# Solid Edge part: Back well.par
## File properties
Username: m_hel
Author: m_hel
Template: Iso Metric Part.par
Last saved by: m_hel
Revision: 10
Application: Solid Edge
Accuracy: 0,990
Material: Textured White
Face Style: White painted
Fill Style: ANSI36(Marble)
Virtual Style: ANSI36(Marble)
Grouping: Uncategorized
LibraryName: Custom Materials
Coef. of Thermal Exp: 0.0
Thermal Conductivity: 0.0
Specific Heat: 0.0
Modulus of Elasticity: 0.0
Poisson's Ratio: 0.0
Yield Stress: 0.0
Ultimate Stress: 0.0
Elongation: 0.0
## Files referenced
..\..\Redfisher18.asm
G:\OneDriveTemp\OneDrive\Dokumendid\TLÜ tööd\3D Modelleerimine\3d modelling\veesõiduk\Deck1.par
G:\OneDriveTemp\OneDrive\Dokumendid\TLÜ tööd\3D Modelleerimine\3d modelling\veesõiduk\Hull.par
iduk\Deck1.par
iduk\Hull.par
iduk\Redfisher18.asm
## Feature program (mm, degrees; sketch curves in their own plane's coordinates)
sketch for "unnamed Protrusion 1" plane through (0, 0, 0) normal (0, 0, 1) x-axis (1, 0, 0)
  line (393.4533, -2800) -> (-393.4533, -2800)
  line (-304.3712, -2294.7906) -> (-393.4533, -2800)
  arc centre (-274.827, -2300) radius 30 from (-274.827, -2270) to (-304.3712, -2294.7906) ccw
  line (274.827, -2270) -> (-274.827, -2270)
  arc centre (274.827, -2300) radius 30 from (304.3712, -2294.7906) to (274.827, -2270) ccw
  line (393.4533, -2800) -> (304.3712, -2294.7906)
extrude "unnamed Protrusion 1" add finite 300 along -normal
thinwall "Thinwall_1"  Thickness = 20 mm
fillet "Round_1" radius 30
lofted protrusion "LoftedProtrusion_1"  StartTangentMagnitude1 = 1; EndTangentMagnitude1 = 1
sketch for "unnamed Cutout 1" plane through (281.2863, -2451.808, -107.6654) normal (-0.984808, -0.173648, 0) x-axis (0.173648, -0.984808, 0)
  circle centre (0, 0) radius 25
extrude "unnamed Cutout 1" cut through along -normal
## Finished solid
Body 1: solid body, 30 faces, 70 edges, 42 vertices.
  Faces by surface: cylinder 11, plane 11, spline 4, sphere 2, torus 2
  Edges by curve: line 38, circle 24, ellipse 4, spline 4
Bounding box of the edges (mm; curved faces can reach further): 827.524 x 550.000 x 320.000, from (-413.7618, -2800, -320) to (413.7618, -2250, 0).
Cylindrical faces by radius (mm): R25 x1, R30 x8, R50 x2
Toroidal faces (ring radius, tube radius in mm): R20 r30 x2
Spherical faces by radius (mm): R30 x2
Planar faces by outward normal: +y 1, +z 2, -y 2, -z 1, oblique 5
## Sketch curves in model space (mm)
circle centre (281.2863, -2451.808, -107.6654) radius 37.5
line (-304.3712, -2294.7906, 0) -> (-393.4533, -2800, 0)
arc centre (-274.827, -2300, 0) radius 30 from (-274.827, -2270, 0) through (-294.1106, -2277.0187, 0) to (-304.3712, -2294.7906, 0)
line (274.827, -2270, 0) -> (-274.827, -2270, 0)
arc centre (274.827, -2300, 0) radius 30 from (304.3712, -2294.7906, 0) through (294.1106, -2277.0187, 0) to (274.827, -2270, 0)
line (393.4533, -2800, 0) -> (304.3712, -2294.7906, 0)
line (393.4533, -2800, 0) -> (-393.4533, -2800, 0)
line (339.2091, -2492.366, -157.6654) -> (339.2091, -2492.366, -57.6654)
line (339.2091, -2492.366, -57.6654) -> (321.8443, -2393.8852, -57.6654)
line (321.8443, -2393.8852, -57.6654) -> (321.8443, -2393.8852, -157.6654)
line (321.8443, -2393.8852, -157.6654) -> (339.2091, -2492.366, -157.6654)
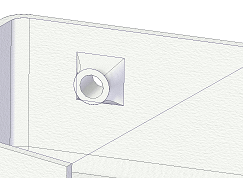
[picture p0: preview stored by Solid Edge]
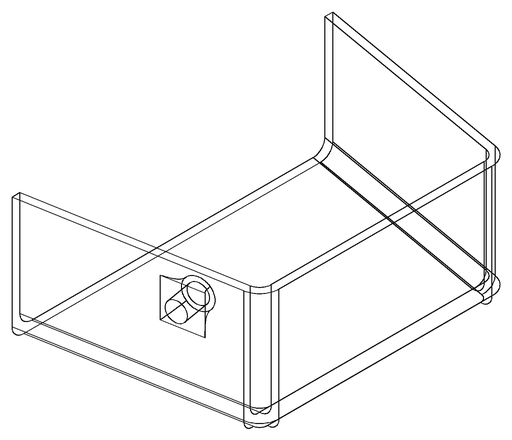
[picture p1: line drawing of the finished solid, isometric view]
